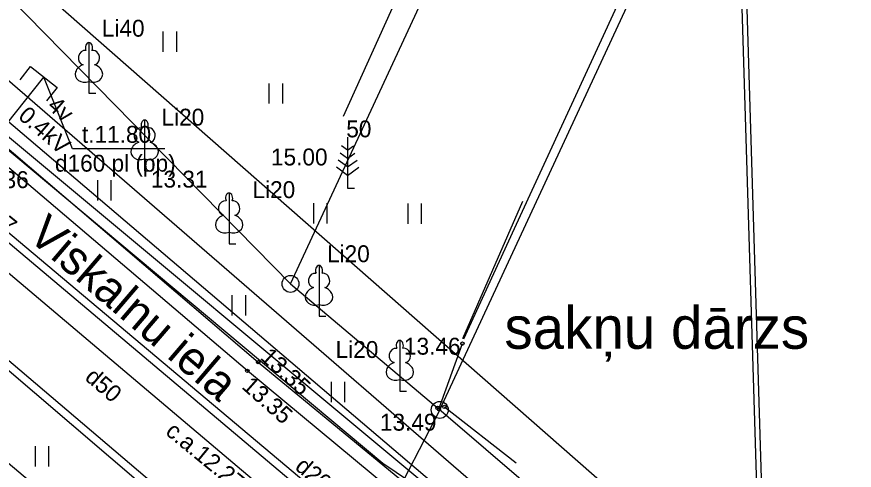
# Model space of a CAD drawing. Extents: x 503877 to 504025, y 304562 to 304725.
# Drawn here: x 503975.24 to 504000, y 304577.15 to 304590.57 of the extents above; entities that cross this region are included whole.
import ezdxf

# ---------------------------------------------------------------- set-up
doc = ezdxf.new("R2010")
doc.units = 0
for name, color, linetype in [('10', 7, 'Continuous'), ('20', 7, 'Continuous'), ('24', 7, 'Continuous'), ('25', 7, 'Continuous'), ('APGS_VADP_ZSPR_####_#', 7, 'Continuous'), ('CELI_CAPM_####_####_#', 7, 'Continuous'), ('CELI_CMAL_####_####_#', 7, 'Continuous'), ('CELI_IELA_####_TKST_#', 7, 'Continuous'), ('CELI_TAKA_####_####_#', 7, 'Continuous'), ('ELEK_VADV_ZSPR_####_#', 7, 'Continuous'), ('ELEK_VADV_ZSPR_TKST_#', 7, 'Continuous'), ('GAZE_VADP_VSP2_####_#', 7, 'Continuous'), ('Level 46', 7, 'Continuous'), ('NORB_ZOGS_ZSTP_####_#', 7, 'Continuous'), ('RELJ_AATZ_####_TKST_#', 7, 'Continuous'), ('RELJ_ELEM_####_####_#', 7, 'Continuous'), ('RELJ_HORZ_PAMT_####_#', 7, 'Continuous'), ('SAKK_KKAN_####_####_#', 7, 'Continuous'), ('SAKT_VADP_KABE_####_#', 7, 'Continuous'), ('SAKT_VADP_NEDR_####_#', 7, 'Continuous'), ('SKAN_ELEM_####_####_#', 7, 'Continuous'), ('SKAN_ELEM_PAST_TKST_#', 7, 'Continuous'), ('SKAN_VADP_PAST_####_I', 7, 'Continuous'), ('SKAN_VADP_PAST_TKST_I', 7, 'Continuous'), ('SKAN_VADP_SPDK_TKST_I', 7, 'Continuous'), ('TERT_DIAM_####_TKST_#', 7, 'Continuous'), ('TERT_ELEM_####_####_#', 7, 'Continuous'), ('TERT_IZMT_####_TKST_#', 7, 'Continuous'), ('TERT_KRND_####_####_#', 7, 'Continuous'), ('UDTK_VADP_NEDR_TKST_#', 7, 'Continuous'), ('UDTK_VADP_UDEN_####_I', 7, 'Continuous')]:
    doc.layers.add(name, color=color, linetype=linetype)

msp = doc.modelspace()

# ---------------------------------------------------------------- linework, layer by layer
at = {"layer": '10'}
for centre in [(503983.332, 304582.665), (503987.744, 304578.935)]:
    msp.add_circle(centre, 0.25, dxfattribs=at)
at = {"layer": '20'}
for p, q in [((503960.823, 304605.633), (503983.332, 304582.665)), ((503987.744, 304578.935), (503985.325, 304574.255))]:
    msp.add_line(p, q, dxfattribs=at)
at = {"layer": '24'}
msp.add_line((503987.744, 304578.935), (504010.166, 304627.354), dxfattribs=at)
at = {"layer": '25'}
for p, q in [((503983.332, 304582.665), (504009.636, 304639.466)), ((503924.947, 304625.297), (503985.325, 304574.255)), ((503983.332, 304582.665), (503987.744, 304578.935))]:
    msp.add_line(p, q, dxfattribs=at)
at = {"layer": 'APGS_VADP_ZSPR_####_#'}
msp.add_line((503955.752, 304593.437), (503977.746, 304575.06), dxfattribs=at)
at = {"layer": 'CELI_CAPM_####_####_#'}
msp.add_line((503982.4, 304573.765), (503968.656, 304585.514), dxfattribs=at)
at = {"layer": 'CELI_CMAL_####_####_#'}
for p, q in [((503982.055, 304580.09), (503962.594, 304596.657)), ((503995.414, 304569.03), (503982.055, 304580.09))]:
    msp.add_line(p, q, dxfattribs=at)
at = {"layer": 'CELI_TAKA_####_####_#'}
for p, q in [((503962.913, 304596.977), (503982.372, 304580.35)), ((503982.372, 304580.35), (503995.836, 304569.27))]:
    msp.add_line(p, q, dxfattribs=at)
at = {"layer": 'ELEK_VADV_ZSPR_####_#'}
msp.add_line((503972.501, 304590.85), (504000, 304566.991), dxfattribs=at)
at = {"layer": 'GAZE_VADP_VSP2_####_#'}
msp.add_line((503971.829, 304583.093), (503992.301, 304565.684), dxfattribs=at)
at = {"layer": 'Level 46'}
msp.add_line((503943.333, 304620.019), (504006.701, 304564.361), dxfattribs=at)
at = {"layer": 'NORB_ZOGS_ZSTP_####_#'}
for p, q in [((503994.532, 304594.264), (503989.947, 304584.295)), ((503989.947, 304584.295), (503988.445, 304581.029)), ((503987.718, 304578.958), (503988.415, 304580.9)), ((503997.768, 304570.323), (503987.718, 304578.958))]:
    msp.add_line(p, q, dxfattribs=at)
at = {"layer": 'RELJ_ELEM_####_####_#'}
for centre in [(503988.415, 304580.9), (503982.372, 304580.35), (503982.055, 304580.09), (503987.674, 304578.997), (503987.718, 304578.958), (503987.884, 304579.024)]:
    msp.add_circle(centre, 0.05, dxfattribs=at)
at = {"layer": 'RELJ_HORZ_PAMT_####_#'}
msp.add_line((503984.894, 304587.628), (503988.762, 304596.208), dxfattribs=at)
at = {"layer": 'SAKK_KKAN_####_####_#'}
for p, q in [((503986.057, 304577.347), (503968.613, 304591.954)), ((503992.108, 304573.299), (503986.057, 304577.347))]:
    msp.add_line(p, q, dxfattribs=at)
at = {"layer": 'SAKT_VADP_KABE_####_#'}
msp.add_line((503991.251, 304573.616), (503971.653, 304590.306), dxfattribs=at)
for points in [[(503997.274, 304571.519), (503996.598, 304593.747)], [(503997.428, 304571.411), (503996.759, 304593.401)]]:
    msp.add_lwpolyline(points, dxfattribs=at)
at = {"layer": 'SAKT_VADP_NEDR_####_#'}
msp.add_line((503997.217, 304568.475), (503924.507, 304629.123), dxfattribs=at)
at = {"layer": 'SKAN_ELEM_####_####_#'}
msp.add_lwpolyline([(503975.337, 304588.708), (503975.647, 304589.1), (503976.431, 304588.478), (503976.12, 304588.087)], dxfattribs=at)
at = {"layer": 'SKAN_VADP_PAST_####_I'}
for p, q in [((503973.287, 304585.319), (503976.039, 304588.789)), ((503995.552, 304566.538), (503973.287, 304585.319))]:
    msp.add_line(p, q, dxfattribs=at)
at = {"layer": 'SKAN_VADP_PAST_TKST_I'}
msp.add_lwpolyline([(503979.615, 304586.663), (503976.882, 304586.663), (503976.039, 304588.789)], dxfattribs=at)
at = {"layer": 'TERT_ELEM_####_####_#'}
for p, q in [((503979.569, 304589.536), (503979.569, 304590.136)), ((503979.969, 304589.536), (503979.969, 304590.136)), ((503977.371, 304588.656), (503977.371, 304588.309)), ((503982.704, 304588.001), (503982.704, 304588.601)), ((503983.104, 304588.001), (503983.104, 304588.601)), ((503977.371, 304588.309), (503977.571, 304588.309)), ((503985.02, 304587.004), (503985.02, 304585.504)), ((503985.02, 304586.628), (503984.844, 304586.756)), ((503985.02, 304586.628), (503985.194, 304586.756)), ((503985.02, 304586.378), (503984.804, 304586.536)), ((503985.02, 304586.378), (503985.236, 304586.536)), ((503979.018, 304586.363), (503979.018, 304586.016)), ((503985.02, 304586.128), (503984.742, 304586.332)), ((503985.02, 304586.128), (503985.298, 304586.332)), ((503979.018, 304586.016), (503979.218, 304586.016)), ((503985.02, 304585.878), (503984.688, 304586.122)), ((503985.02, 304585.878), (503985.354, 304586.122)), ((503977.633, 304585.137), (503977.633, 304585.737)), ((503978.033, 304585.137), (503978.033, 304585.737)), ((503985.02, 304585.504), (503985.22, 304585.504)), ((503984.017, 304584.456), (503984.017, 304585.056)), ((503984.417, 304584.456), (503984.417, 304585.056)), ((503986.809, 304584.445), (503986.809, 304585.045)), ((503987.209, 304584.445), (503987.209, 304585.045)), ((503981.516, 304584.201), (503981.516, 304583.854)), ((503981.516, 304583.854), (503981.716, 304583.854)), ((503981.61, 304581.733), (503981.61, 304582.333)), ((503982.01, 304581.733), (503982.01, 304582.333)), ((503984.175, 304582.058), (503984.175, 304581.711)), ((503984.175, 304581.711), (503984.375, 304581.711)), ((503984.54, 304579.167), (503984.54, 304579.767)), ((503984.94, 304579.167), (503984.94, 304579.767)), ((503986.562, 304579.838), (503986.562, 304579.491)), ((503986.562, 304579.491), (503986.762, 304579.491)), ((503975.788, 304577.259), (503975.788, 304577.859)), ((503976.188, 304577.259), (503976.188, 304577.859))]:
    msp.add_line(p, q, dxfattribs=at)
for points in [[(503977.371, 304589.809), (503977.371, 304588.656)], [(503977.461, 304589.577), (503977.46, 304589.578)], [(503979.018, 304587.516), (503979.018, 304586.363)], [(503979.108, 304587.284), (503979.107, 304587.285)], [(503981.516, 304585.354), (503981.516, 304584.201)], [(503981.606, 304585.122), (503981.605, 304585.123)], [(503984.175, 304583.211), (503984.175, 304582.058)], [(503984.265, 304582.979), (503984.264, 304582.98)], [(503986.562, 304580.991), (503986.562, 304579.838)], [(503986.652, 304580.759), (503986.651, 304580.76)]]:
    msp.add_lwpolyline(points, dxfattribs=at)
for centre, major_axis, ratio, start_param, end_param in [((503977.371, 304589.659), (0, -0.15), 0.707107, 3.14537, 5.287485), ((503977.371, 304589.659), (0, -0.15), 0.707107, 0.995701, 3.137816), ((503977.243, 304589.364), (-0.039, -0.212), 0.861323, 3.141593, 6.283185), ((503977.499, 304589.364), (0.039, -0.212), 0.861323, 0, 3.141593), ((503977.281, 304588.902), (0.307, 0.095), 0.814445, 1.570796, 4.752015), ((503977.461, 304588.902), (-0.307, 0.095), 0.814445, 1.531171, 4.712389), ((503979.018, 304587.366), (0, -0.15), 0.707107, 3.14537, 5.287485), ((503979.018, 304587.366), (0, -0.15), 0.707107, 0.995701, 3.137816), ((503978.89, 304587.071), (-0.039, -0.212), 0.861323, 3.141593, 6.283185), ((503979.146, 304587.071), (0.039, -0.212), 0.861323, 0, 3.141593), ((503978.928, 304586.609), (0.307, 0.095), 0.814445, 1.570796, 4.752015), ((503979.108, 304586.609), (-0.307, 0.095), 0.814445, 1.531171, 4.712389), ((503981.516, 304585.204), (0, -0.15), 0.707107, 3.14537, 5.287485), ((503981.516, 304585.204), (0, -0.15), 0.707107, 0.995701, 3.137816), ((503981.388, 304584.909), (-0.039, -0.212), 0.861323, 3.141593, 6.283185), ((503981.644, 304584.909), (0.039, -0.212), 0.861323, 0, 3.141593), ((503981.426, 304584.447), (0.307, 0.095), 0.814445, 1.570796, 4.752015), ((503981.606, 304584.447), (-0.307, 0.095), 0.814445, 1.531171, 4.712389), ((503984.175, 304583.061), (0, -0.15), 0.707107, 3.14537, 5.287485), ((503984.175, 304583.061), (0, -0.15), 0.707107, 0.995701, 3.137816), ((503984.047, 304582.766), (-0.039, -0.212), 0.861323, 3.141593, 6.283185), ((503984.303, 304582.766), (0.039, -0.212), 0.861323, 0, 3.141593), ((503984.085, 304582.304), (0.307, 0.095), 0.814445, 1.570796, 4.752015), ((503984.265, 304582.304), (-0.307, 0.095), 0.814445, 1.531171, 4.712389), ((503986.562, 304580.841), (0, -0.15), 0.707107, 3.14537, 5.287485), ((503986.562, 304580.841), (0, -0.15), 0.707107, 0.995701, 3.137816), ((503986.434, 304580.546), (-0.039, -0.212), 0.861323, 3.141593, 6.283185), ((503986.69, 304580.546), (0.039, -0.212), 0.861323, 0, 3.141593), ((503986.472, 304580.084), (0.307, 0.095), 0.814445, 1.570796, 4.752015), ((503986.652, 304580.084), (-0.307, 0.095), 0.814445, 1.531171, 4.712389)]:
    msp.add_ellipse(centre, major_axis=major_axis, ratio=ratio, start_param=start_param, end_param=end_param, dxfattribs=at)
at = {"layer": 'TERT_KRND_####_####_#'}
msp.add_line((503987.884, 304579.024), (503990.006, 304577.366), dxfattribs=at)
msp.add_lwpolyline([(503988.431, 304581.045), (503990.202, 304585.11)], dxfattribs=at)
at = {"layer": 'UDTK_VADP_UDEN_####_I'}
msp.add_line((504000, 304563.139), (503968.511, 304589.634), dxfattribs=at)

# ---------------------------------------------------------------- texts
at = {"layer": 'CELI_IELA_####_TKST_#'}
msp.add_text('Viskalnu iela', height=1, rotation=319.4639, dxfattribs=at).set_placement((503975.521, 304584.028))
at = {"layer": 'ELEK_VADV_ZSPR_TKST_#'}
for s, p in [('0.4kV', (503975.248, 304587.587)), ('4v', (503976.11, 304587.88))]:
    msp.add_text(s, height=0.5, rotation=319.0539, dxfattribs=at).set_placement(p)
at = {"layer": 'RELJ_AATZ_####_TKST_#'}
for s, p in [(' 15.00', (503982.568, 304586.172)), (' 13.31', (503979.018, 304585.516)), (' 13.46', (503986.501, 304580.571)), (' 13.49', (503985.789, 304578.321))]:
    msp.add_text(s, height=0.5, dxfattribs=at).set_placement(p)
for rotation, p in [(317.4052, (503982.273, 304580.583)), (318.4585, (503981.723, 304579.716))]:
    msp.add_text(' 13.35', height=0.5, rotation=rotation, dxfattribs=at).set_placement(p)
at = {"layer": 'SKAN_ELEM_PAST_TKST_#'}
msp.add_text(' 13.36', height=0.5, dxfattribs=at).set_placement((503973.733, 304585.501))
at = {"layer": 'SKAN_VADP_PAST_TKST_I'}
for s, rotation, p in [('t.11.80', 360, (503977.165, 304586.842)), ('t9.47', 320.8143, (503973.825, 304585.036)), ('d200 pl(PP)', 319.8517, (503983.433, 304577.202))]:
    msp.add_text(s, height=0.5, rotation=rotation, dxfattribs=at).set_placement(p)
msp.add_text('d160 pl (pp)', height=0.5, dxfattribs=at).set_placement((503976.367, 304585.988))
at = {"layer": 'SKAN_VADP_SPDK_TKST_I'}
msp.add_text('c.a.12.27', height=0.5, rotation=320.6077, dxfattribs=at).set_placement((503979.603, 304578.237))
at = {"layer": 'TERT_DIAM_####_TKST_#'}
for s, p in [('Li40', (503977.752, 304589.983)), ('Li20', (503979.517, 304587.351)), (' 50', (503984.795, 304587.004)), ('Li20', (503982.206, 304585.205)), ('Li20', (503984.411, 304583.308)), ('Li20', (503984.665, 304580.473))]:
    msp.add_text(s, height=0.5, dxfattribs=at).set_placement(p)
at = {"layer": 'TERT_IZMT_####_TKST_#'}
msp.add_text('sakņu dārzs', height=1.25, dxfattribs=at).set_placement((503989.656, 304580.745))
at = {"layer": 'UDTK_VADP_NEDR_TKST_#'}
msp.add_text('d50', height=0.5, rotation=319.2766, dxfattribs=at).set_placement((503977.221, 304579.849))

doc.saveas('drawing.dxf')
